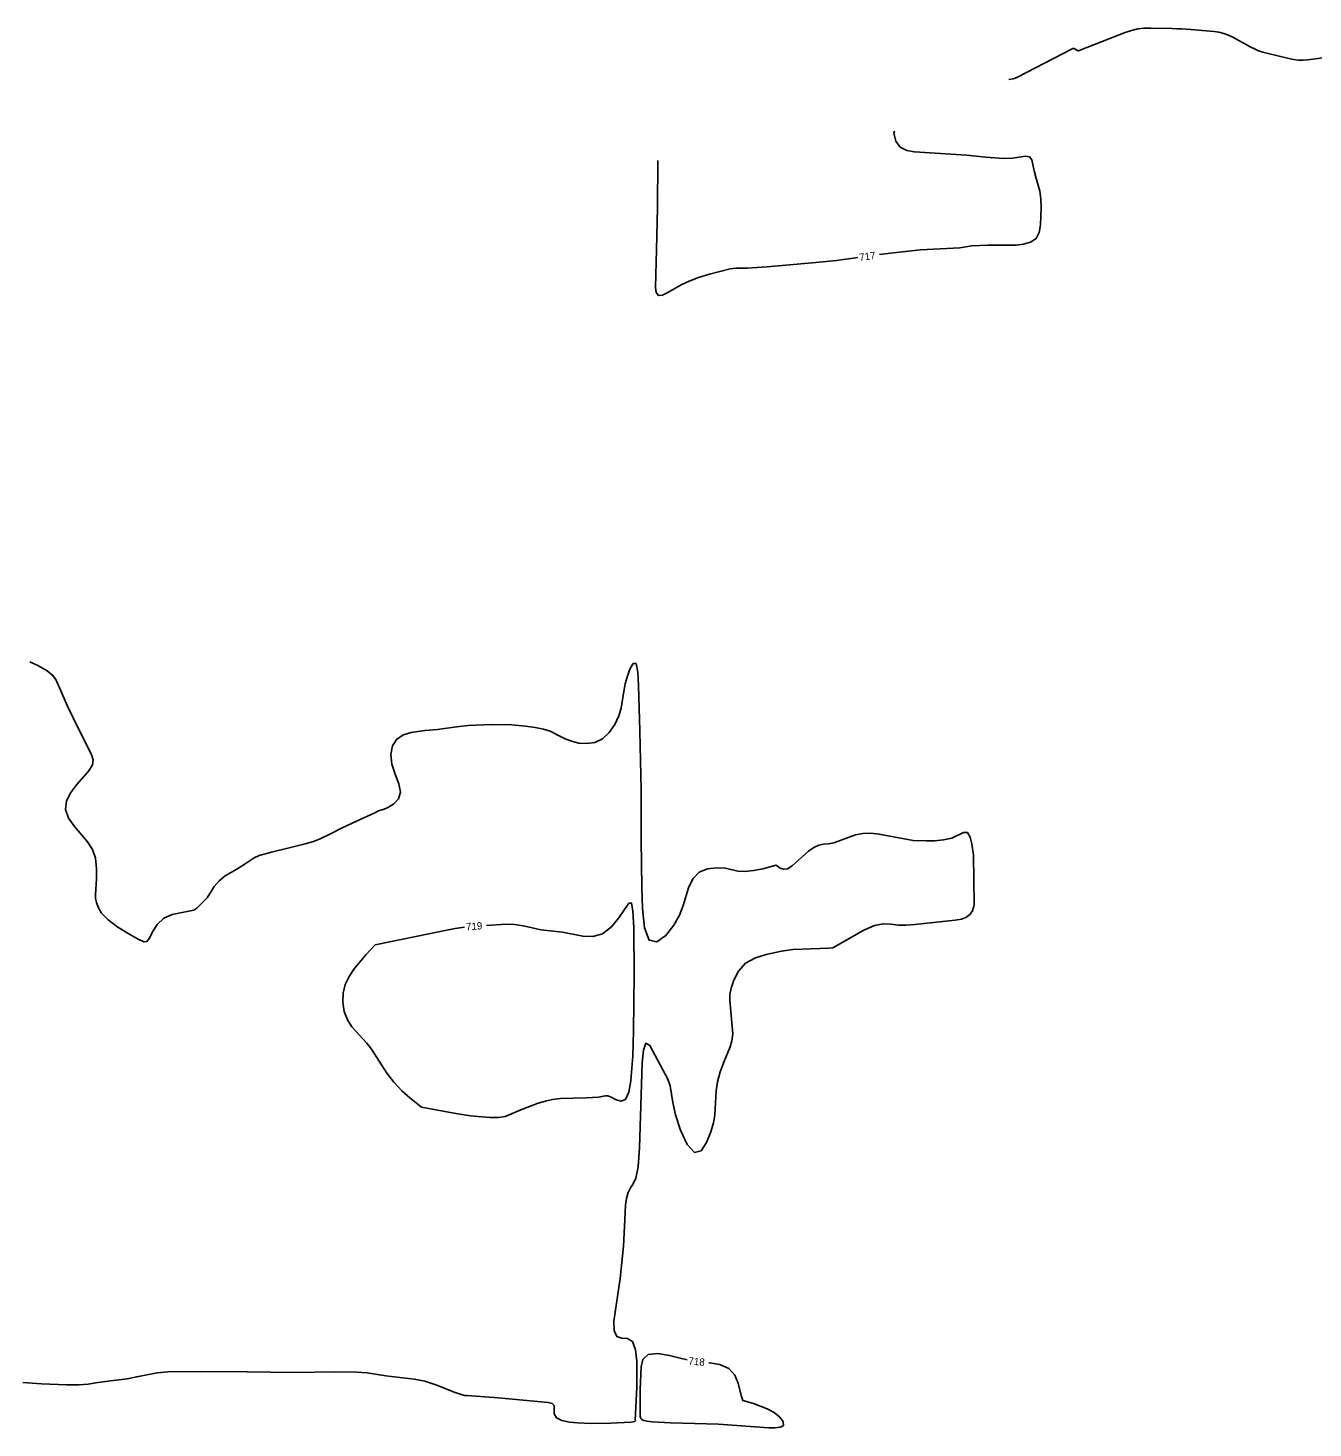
# Model space of a CAD drawing. Extents: x -361782338 to 28259792, y -263199453 to 8342113.
# Drawn here: x 1402184 to 1402889, y 576411 to 577178 of the extents above; entities that cross this region are included whole.
import ezdxf

# ---------------------------------------------------------------- set-up
doc = ezdxf.new("R2010")
doc.units = 0
doc.layers.add('DT_X_Contour_Minor', color=7, linetype='Continuous')
doc.layers.add('Level 19', color=7, linetype='Continuous')

msp = doc.modelspace()

# ---------------------------------------------------------------- linework, layer by layer
at = {"layer": 'DT_X_Contour_Minor'}
for points in [[(1402721.78, 577150), (1402724.21, 577150.41), (1402724.73, 577150.51), (1402725.23, 577150.66), (1402725.72, 577150.85), (1402726.2, 577151.07), (1402756.51, 577166.9), (1402756.91, 577167.06), (1402757.31, 577167.09), (1402757.69, 577167.01), (1402758.07, 577166.82), (1402759.3, 577166), (1402759.57, 577165.86), (1402759.84, 577165.79), (1402760.13, 577165.8), (1402760.42, 577165.88), (1402785.59, 577175.78), (1402788.99, 577176.93), (1402792.45, 577177.72), (1402795.97, 577178.16), (1402799.56, 577178.24), (1402811.37, 577177.93), (1402813.9, 577177.84), (1402816.43, 577177.72), (1402818.96, 577177.55), (1402821.48, 577177.35), (1402834.28, 577176.24), (1402836.98, 577175.87), (1402839.6, 577175.23), (1402842.14, 577174.32), (1402844.6, 577173.14), (1402854.4, 577167.81), (1402856.53, 577166.74), (1402858.72, 577165.81), (1402860.95, 577165.03), (1402863.25, 577164.39), (1402875.31, 577161.46), (1402877.9, 577160.95), (1402880.51, 577160.69), (1402883.12, 577160.66), (1402885.75, 577160.88), (1402900.65, 577162.77)], [(1402651.04, 577054.03), (1402656.94, 577054.83), (1402673.46, 577056.59), (1402694.92, 577057.79), (1402701.47, 577058.92), (1402710.18, 577059.3), (1402725.79, 577059.3), (1402729.84, 577059.76), (1402733.73, 577060.86), (1402736.79, 577062.93), (1402738.54, 577066.21), (1402739.27, 577070.4), (1402739.48, 577079.83), (1402739.3, 577084.48), (1402738.76, 577088.85), (1402736.63, 577096.45), (1402735.65, 577099.9), (1402734.42, 577105.9), (1402733.23, 577107.58), (1402731.05, 577107.93), (1402723.76, 577106.9), (1402718.91, 577106.8), (1402709.26, 577107.51), (1402698.64, 577108.49), (1402670.07, 577110.29), (1402665.96, 577111.15), (1402662.37, 577113), (1402659.84, 577116.2), (1402658.88, 577120.55), (1402659.13, 577121.69)], [(1402529.52, 577105.7), (1402529.32, 577079.6), (1402528.83, 577056.82), (1402528.23, 577035.95), (1402528.64, 577033.21), (1402529.8, 577031.59), (1402531.98, 577031.78), (1402534.96, 577033.32), (1402542.26, 577037.53), (1402546.58, 577039.52), (1402551.76, 577041.47), (1402557.87, 577043.38), (1402569.1, 577046.16), (1402572.42, 577046.56), (1402578.42, 577046.53), (1402589.49, 577047.28), (1402616.1, 577049.69), (1402627.36, 577050.82), (1402639.15, 577052.42)], [(1402185.3, 576830.87), (1402189.69, 576828.85), (1402194.87, 576825.94), (1402197.99, 576823.44), (1402199.74, 576820.82), (1402205.97, 576806.57), (1402211.97, 576794.08), (1402219.24, 576780.06), (1402220.16, 576777.14), (1402219.73, 576774.34), (1402217.72, 576771.2), (1402211.07, 576763.66), (1402207.76, 576759.32), (1402205.44, 576754.72), (1402204.89, 576749.98), (1402206.6, 576745.23), (1402209.85, 576740.6), (1402217.03, 576732.21), (1402219.69, 576728.05), (1402221.38, 576723.25), (1402221.98, 576717.55), (1402221.85, 576711.71), (1402221.27, 576703.4), (1402221.37, 576701.1), (1402221.82, 576698.97), (1402222.77, 576696.32), (1402224.72, 576693.09), (1402228.24, 576689.4), (1402233.58, 576685.45), (1402239.56, 576681.76), (1402244.67, 576678.93), (1402247.8, 576677.49), (1402249.53, 576677.63), (1402250.85, 576679.47), (1402252.61, 576682.91), (1402255.16, 576686.96), (1402258.74, 576690.4), (1402263.37, 576692.34), (1402275.19, 576694.67), (1402276.86, 576695.79), (1402282.45, 576701.51), (1402286.46, 576707.67), (1402289.12, 576710.88), (1402292.33, 576713.53), (1402298.73, 576717.3), (1402302.85, 576719.81), (1402308.28, 576723.5), (1402310.95, 576724.71), (1402317.77, 576726.59), (1402327.5, 576728.85), (1402336.3, 576731.07), (1402340.87, 576732.42), (1402344.55, 576733.79), (1402350.21, 576736.62), (1402356.19, 576739.79), (1402364.42, 576743.58), (1402374.46, 576748.19), (1402376.42, 576749.25), (1402379.53, 576750.14), (1402381.97, 576751.2), (1402384.88, 576753.02), (1402387.41, 576755.72), (1402388.52, 576759.38), (1402387.59, 576764), (1402385.54, 576769.26), (1402383.69, 576774.76), (1402383.13, 576780.08), (1402384.05, 576784.81), (1402386.43, 576788.51), (1402390.1, 576790.89), (1402394.4, 576792.19), (1402401.88, 576793.14), (1402408.67, 576793.79), (1402419.15, 576795.27), (1402425.54, 576795.95), (1402438.45, 576796.47), (1402449.48, 576796.37), (1402457.06, 576795.58), (1402462.19, 576794.84), (1402466.92, 576793.89), (1402470.46, 576792.78), (1402475.76, 576790.13), (1402478.73, 576788.67), (1402482.19, 576787.33), (1402486.13, 576786.36), (1402490.47, 576786.02), (1402494.92, 576786.65), (1402499.14, 576788.62), (1402502.84, 576792.11), (1402505.85, 576796.56), (1402508.06, 576801.2), (1402509.4, 576805.42), (1402510.54, 576812.48), (1402511.55, 576818.73), (1402512.6, 576822.47), (1402514.21, 576826.76), (1402516.01, 576829.93), (1402517.56, 576829.88), (1402518.51, 576825.27), (1402518.97, 576817.94), (1402519.56, 576792.92)], [(1402519.56, 576792.92), (1402520.32, 576760.76), (1402520.42, 576733.2), (1402520.77, 576707.14), (1402521.12, 576695.74), (1402522.21, 576685.1), (1402524.68, 576678.27), (1402528.88, 576677.4), (1402533.86, 576680.96), (1402538.34, 576686.53), (1402541.37, 576692.11), (1402543.3, 576697.4), (1402546.48, 576707.61), (1402548.8, 576712.11), (1402552.15, 576715.51), (1402556.73, 576717.4), (1402561.81, 576718.01), (1402566.49, 576717.73), (1402573.39, 576716.16), (1402577.14, 576715.88), (1402581.96, 576716.44), (1402587.01, 576717.49), (1402594.33, 576719.34), (1402596.52, 576717.8), (1402598.31, 576717.18), (1402600.54, 576717.45), (1402603.14, 576719.08), (1402611.98, 576727.1), (1402614.92, 576729.16), (1402617.71, 576730.46), (1402620.31, 576730.94), (1402622.96, 576731.11), (1402625.98, 576731.6), (1402637.73, 576735.98), (1402641.89, 576736.78), (1402646.19, 576736.89), (1402650.83, 576736.42), (1402669.39, 576733.01), (1402676.56, 576732.79), (1402681.14, 576732.84), (1402686.06, 576733.22), (1402690.63, 576734.23), (1402697.08, 576737.38), (1402699.14, 576737.27), (1402700.61, 576734.82), (1402701.59, 576731.03), (1402702.39, 576724.82), (1402702.77, 576697.79), (1402702.56, 576696.18), (1402701.9, 576694.38), (1402700.65, 576692.52), (1402698.67, 576690.95), (1402695.87, 576689.91), (1402692.38, 576689.27), (1402670.25, 576686.87), (1402665.66, 576686.55), (1402661.32, 576686.62), (1402657.26, 576687.09), (1402653.07, 576687.28), (1402648.2, 576686.35), (1402642.41, 576683.75), (1402625.39, 576674.1), (1402623.11, 576673.85), (1402603.48, 576673.18), (1402597.25, 576672.35), (1402588.88, 576670.48), (1402583.02, 576668.63), (1402577.6, 576665.64), (1402573.65, 576661.35), (1402571.11, 576656.47), (1402569.65, 576651.96), (1402568.97, 576648.45), (1402568.89, 576645.33), (1402570.53, 576626.99), (1402570.08, 576623.22), (1402569.04, 576619.92), (1402565.57, 576611.54), (1402563.66, 576606.18), (1402562.18, 576600.73), (1402561.42, 576595.67), (1402560.76, 576582.59), (1402560.03, 576578.25), (1402558.59, 576573.2), (1402556.25, 576567.43), (1402553.15, 576562.9), (1402549.5, 576562.03), (1402545.59, 576566.41), (1402541.95, 576574.16), (1402539.21, 576582.52), (1402537.74, 576589.29), (1402536.33, 576598.53), (1402535.04, 576602.05), (1402525.12, 576620.62), (1402522.91, 576621.84), (1402521.6, 576617.97), (1402520.97, 576611.05), (1402520.09, 576587.53), (1402519.43, 576564.62), (1402518.65, 576554.18), (1402517.4, 576547.9), (1402515.9, 576544.69)], [(1402435.6, 576686.43), (1402446.47, 576687.12), (1402450.91, 576686.9), (1402455.82, 576686.09), (1402465.38, 576683.98), (1402472.15, 576683.16), (1402477.32, 576682.7), (1402488.48, 576680.57), (1402493.8, 576680.35), (1402499.17, 576681.83), (1402504.05, 576685.6), (1402508.21, 576690.63), (1402513.68, 576698.56), (1402515.07, 576698.65), (1402515.88, 576694.37), (1402516.33, 576685.02), (1402516.55, 576659.25), (1402516.13, 576628.7), (1402515.72, 576614.77), (1402515.32, 576608.18), (1402514.65, 576601.27), (1402513.51, 576595.1), (1402511.71, 576591.04), (1402509.17, 576589.99), (1402506.35, 576590.92), (1402503.83, 576592.32), (1402502.02, 576592.98), (1402500.6, 576592.98), (1402496.95, 576592.36), (1402490.4, 576591.97), (1402476.08, 576591.47), (1402471.83, 576590.97), (1402467.91, 576590.16), (1402463.91, 576588.99), (1402455.31, 576585.75), (1402445.83, 576581.66), (1402442.32, 576581.11), (1402437.51, 576581.1), (1402426.82, 576582.02), (1402418.83, 576583.26), (1402400, 576586.79), (1402393.68, 576591.86), (1402389.21, 576595.81), (1402384.74, 576600.44), (1402380.99, 576605.38), (1402372.63, 576618.58), (1402370.08, 576621.87), (1402361.73, 576630.89), (1402359.35, 576634.65), (1402357.69, 576639.21), (1402356.89, 576644.26), (1402357.06, 576649.32), (1402358.24, 576654.03), (1402360.31, 576658.42), (1402363.07, 576662.63), (1402369.46, 576670.33), (1402374.66, 576675.77), (1402382.55, 576677.41), (1402410.18, 576683), (1402418.48, 576684.79), (1402423.64, 576685.51)], [(1402515.9, 576544.69), (1402514.43, 576542.58), (1402513.22, 576539.98), (1402512.34, 576536.78), (1402511.79, 576533.27), (1402511.44, 576525.01), (1402510.64, 576510.58), (1402508.84, 576492.84), (1402505.42, 576469.45), (1402505.62, 576464.44), (1402506.97, 576461.16), (1402509.66, 576460.2), (1402512.91, 576459.97), (1402515.7, 576458.32), (1402517.29, 576453.78), (1402517.9, 576447.63), (1402518.01, 576433.55), (1402517.19, 576418.46), (1402517.01, 576415.41), (1402517.35, 576414.99), (1402516.97, 576414.59), (1402514.72, 576414.23), (1402503.7, 576413.67), (1402493, 576413.47), (1402485.45, 576413.79), (1402481.11, 576414.2), (1402476.93, 576415.02), (1402473.92, 576416.48), (1402472.77, 576418.69), (1402472.62, 576423.2), (1402471.58, 576424.39), (1402469.42, 576424.94), (1402442.04, 576427.57), (1402424.98, 576428.76), (1402423.63, 576428.83), (1402421.67, 576429.24), (1402418.5, 576430.34), (1402407.93, 576434.64), (1402401.82, 576436.61), (1402396.03, 576437.74), (1402380.47, 576439.54), (1402370.16, 576441.2), (1402364.48, 576441.62), (1402352.44, 576441.69), (1402330.4, 576441.36), (1402304.45, 576441.7), (1402278.9, 576441.86), (1402260.96, 576441.7), (1402255.11, 576441.18), (1402243.96, 576439.04), (1402238.79, 576437.99), (1402229.49, 576436.79), (1402221.47, 576435.67), (1402217.26, 576435.03), (1402212.07, 576434.61), (1402205.51, 576434.55), (1402191.67, 576435.12), (1402181.6, 576435.9)], [(1402545.62, 576448.36), (1402541.7, 576449.3), (1402535.88, 576450.77), (1402529.51, 576451.79), (1402524.26, 576451.27), (1402521.36, 576448.56), (1402520.29, 576444.54), (1402519.85, 576432.03), (1402519.87, 576424.9), (1402519.85, 576417.22), (1402520.14, 576416.19), (1402520.72, 576415.56), (1402521.73, 576415.06), (1402523.52, 576414.62), (1402526.47, 576414.28), (1402536.35, 576413.84), (1402562.75, 576413), (1402590.37, 576410.96), (1402593.58, 576410.97), (1402596.62, 576411.33), (1402598.44, 576412.39), (1402598.25, 576414.37), (1402596.32, 576416.89), (1402593.17, 576419.42), (1402589.33, 576421.54), (1402581.9, 576424.36), (1402576.03, 576426.03), (1402575.2, 576428.8), (1402573.53, 576435.44), (1402571.65, 576439.85), (1402568.37, 576443.56), (1402563.44, 576445.74), (1402557.8, 576446.72), (1402557.52, 576446.75)]]:
    msp.add_lwpolyline(points, dxfattribs=at)

# ---------------------------------------------------------------- texts
at = {"layer": 'Level 19'}
for s, rotation, p in [('717', 7.7292, (1402640.15, 577050.53)), ('719', 3.65547, (1402424.5, 576683.71)), ('718', 354.5692, (1402546.13, 576445.82))]:
    msp.add_text(s, height=4, rotation=rotation, dxfattribs=at).set_placement(p)

doc.saveas('drawing.dxf')
